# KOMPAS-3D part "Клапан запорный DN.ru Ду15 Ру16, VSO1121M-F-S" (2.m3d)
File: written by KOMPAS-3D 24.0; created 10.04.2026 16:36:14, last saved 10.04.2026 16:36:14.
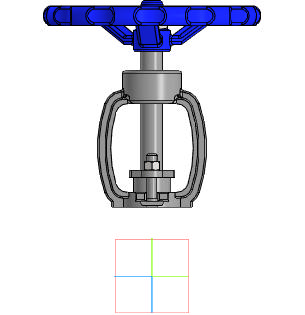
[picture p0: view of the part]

Document properties: Автор: R2D2; Полное имя файла: E:\Работа\Зайцев\VSO3131M-F-S Клапан запорный DN.ru Ду15-100 Ру40\DN15\исходные материалы\2.m3d

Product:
- Component [assembly]: Сборка  | qty 1  | pos. 1  | Масса: 0.728984; Автор: R2D2; source file: dn15_3d_step.a3d
- Body: Тело 1  | qty 1
    Масса: 0.715787
- Component [standard]: Фланец 15-1-01-1-B-ВЧ40-I-dв 19 ГОСТ 33259-2015  | qty 1  | Раздел спецификации: Стандартные изделия; additional columns: BOSimple***Material:38d6725a-5efe-48e1-b177-a7817acb862a
- Part/product: Клапан запорный DN.ru Ду15 Ру16  | designation VSO1121M-F-S
    Масса: 3.1
    Раздел спецификации: Прочие изделия
    Примечание: D090-01942

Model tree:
1. Эскиз:1
2. Элемент выдавливания:1  (labels: Грань.Твердое тело1)
     Расстояние 1 = 25.9987; Смещение 1 = 1
3. Эскиз:2  (with: Ребро.Элемент выдавливания:1)
4. Элемент выдавливания:2
     Расстояние 1 = 500
5. Эскиз:3
6. Элемент выдавливания:3  (with: Грань.Элемент выдавливания:1)  (labels: Грань.Твердое тело1; Твердое тело1; Solid1)
     Расстояние 1 = 500; Расстояние = 40

Referenced files in E:\Работа\Зайцев\VSO3131M-F-S Клапан запорный DN.ru Ду15-100 Ру40\DN15\исходные материалы\: dn15_3d_step.a3d
Referenced files in C:\Program Files\ASCON\KOMPAS-3D v24\Libs\PolynomLib\DATA\vault\Methods\Kompas\3D\: PLib_Flange_GOST_33259_1401.m3d
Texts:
  BOSimple***Material:38d6725a-5efe-48e1-b177-a7817acb862a
  BOSimple***PART:3f5f0d7e-d4da-47dc-6145-6a7f26b7079a***SHORTLOC:B6A6_23E38AE8DB154823[I;1;Круглый;15;1;19;0;ВЧ40 ГОСТ 7293-85]
  VSO1121M-F-S
  DN15
  GOST 26.020 Pr3
  PN40
  ВЧ40 ГОСТ 7293-85
  Ch34
  Ось Z.Начало координат
  Ось Y.Начало координат
  Плоскость ZX.Начало координат
  Plane ZX. Origin
  Плоскость ZY.Начало координат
